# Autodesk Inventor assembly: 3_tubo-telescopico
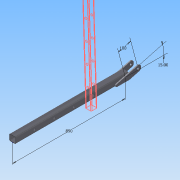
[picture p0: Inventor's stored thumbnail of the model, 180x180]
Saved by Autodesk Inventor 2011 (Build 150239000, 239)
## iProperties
Created: 2020-12
Part Number: 3_tubo-telescopico
Document SubType Name: Assembly
Designer: PC
Mass: 5720.53 g
Surface Area: 3460.76 cm^2
Volume: 728.581 cm^3
Density: 7.8516 g/cm^3
_SolveAssemblyDoc: Frame Generator Solve Assembly
_Version: 15.0.0
Author: PC
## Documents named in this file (3)
- C:\Users\PC\Documents\Inventor\workshop-crane-powered-by-drill\3_tubo-telescopico.iam
- C:\Users\PC\Documents\Inventor\workshop-crane-powered-by-drill\3_tubo-telescopico_esqueleto.ipt
- C:\Users\PC\Documents\Inventor\workshop-crane-powered-by-drill\3_tubo-telescopico\Frame\Frame0001.iam
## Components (2 placed, 2 different names)
1. 3_tubo-telescopico_esqueleto:1
2. Frame0001:1 [sub-assembly]
